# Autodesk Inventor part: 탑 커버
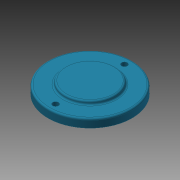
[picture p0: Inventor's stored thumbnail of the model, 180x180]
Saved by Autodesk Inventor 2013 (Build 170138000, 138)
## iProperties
Created: 2017-05
Part Number: 탑 커버
Material: 알루미늄 6061
Document SubType Name: Modeling
Designer: mduedu
Density: 1 g/cm^3
Author: mduedu
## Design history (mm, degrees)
sketch "스케치1"
  geometry: C1 r 25 at (0, 0); 1 further point
  constraints: 1 centre point, 1 coincident
  dimensions: "d31" = 50 diameter of C1
extrude "돌출1" new body sketch "스케치1" distance "d2" = 5; taper "d3" = 0 deg
sketch "스케치2"
  geometry: C1 r 15 at (0, 0); 1 further point
  constraints: 1 centre point, 1 coincident
  dimensions: "d5" = 30 diameter of C1
extrude "돌출2" join sketch "스케치2" distance "d6" = 2; taper "d7" = 0 deg
sketch "스케치3"
  geometry: C1 r 16 at (0, 0); 1 further point
  constraints: 1 centre point, 1 coincident
  dimensions: "d32" = 32 diameter of C1
extrude "돌출3" join sketch "스케치3" distance "d10" = 3; taper "d11" = 0 deg
sketch "스케치4"
  geometry: C1 r 16 at (0, 0) reference; C2 r 14 at (0, 0); 1 further point
  constraints: 1 centre point
  dimensions: "d33" = 2 radial gap between concentric circles of C2 C1
extrude "돌출4" cut sketch "스케치4" distance "d14" = 6; taper "d15" = 0 deg
chamfer "모따기1" distance "d16" = 1; stored, may be unused: second distance "d17" = 2, angle "d18" = 45 deg
fillet "모깎기3" dims "d19" = 1
fillet "모깎기4" dims "d20" = 1
fillet "모깎기5" dims "d21" = 1
sketch "스케치5" dims "d34" = 41
  geometry: C1 r 25 at (0, 0) reference; 2 further points
  constraints: 2 vertical alignment, 1 coincident, 2 other
hole "구멍2" sketch "스케치5" at (0, 20.5) diameter "d35" = 3.4; stored, may be unused: countersink angle "d39" = 90 deg, drill point angle "d41" = 118 deg; dims "d36" = 6, "d37" = 4, "d38" = 2, "d40" = 8
node "솔리드1"
pattern_circular "원형 패턴1" dims angle "d43" = 360 deg
node "투영된 루프2"
